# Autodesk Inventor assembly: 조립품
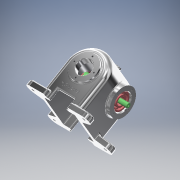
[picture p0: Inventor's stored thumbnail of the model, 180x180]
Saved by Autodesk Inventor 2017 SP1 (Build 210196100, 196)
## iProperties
Part Number: 조립품
Material: 일반
Document SubType Name: Assembly
Designer: MRC
Author: MRC
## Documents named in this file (4)
- C:\Users\MRC\Desktop\740904V1016\조립품.iam
- C:\Users\MRC\Desktop\740904V1016\본체.ipt
- C:\Users\MRC\Desktop\740904V1016\깊은 홈 볼베어링 6203.ipt
- C:\Users\MRC\Desktop\740904V1016\편심축.ipt
